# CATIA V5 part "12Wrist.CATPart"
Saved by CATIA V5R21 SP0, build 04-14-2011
Part number: Wrist
Bounding box of the stored display mesh (mm): x -30 to 20.5, y -302.172 to -247.172, z 287.191 to 317.191
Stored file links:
  C:\Users\水心\Desktop\Arm_Detailed_Design_Assembly_Manu\12Wrist.CATPart
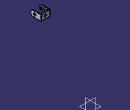
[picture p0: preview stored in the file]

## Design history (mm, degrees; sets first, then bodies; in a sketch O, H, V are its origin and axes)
Body1 (main body)
  DatumSurface1
  DatumCurve1
  DatumCurve2
  Plane1: stored without definition
  Plane2: stored without definition
  DatumCurve3
  Sketch1 on face of DatumSurface1, origin (0, -247.172, 0), H (-1, 0, 0), V (0, 0, 1)
    circle A1 centre (3, 310.6906) radius 1.25
    reference projected circle E1 centre (3, 310.6906) radius 1.25 from edge of DatumCurve2
    circle A2 centre (-5.5, 302.1906) radius 1.25
    circle A3 centre (3, 293.6906) radius 1.25
    circle A4 centre (11.5, 302.1906) radius 1.25
    line L1 (27, 317.1906) -> (-17.5, 317.1906)
    line L2 (-17.5, 317.1906) -> (-17.5, 287.1906)
    line L3 (-17.5, 287.1906) -> (27, 287.1906)
    line L4 (27, 287.1906) -> (27, 317.1906)
    reference intersected line E2 through (0, 302.1906) direction (-1, 0) from Plane1
    reference intersected line E3 through (3, 0) direction (0, -1) from Plane2
    circle A5 centre (3, 302.1906) radius 6
    reference projected circle E4 centre (3, 302.1906) radius 6 from edge of DatumCurve3
    length L2 = 30
    distance L1 E2 = 15
    length L3 = 44.5
    distance L2 E3 = 20.5
    coincidence: A1 E1, A5 E4
    horizontal: L1 H, L3 H
    vertical: L2 V, L4 V
  Pad1: profile Sketch1, direction (0, -1, 0), length 5
  Plane3 to Plane6: stored without definition
  DatumSurface2
  DatumSurface3
  Sketch2 on face of Pad1 from Sketch1.L2, origin (17.5, 0, 0), H (0, 1, 0), V (0, 0, 1)
    circle A1 centre (-249.672, 307.1906) radius 1.25
    point P1 (-249.672, 307.1906)
    circle A2 centre (-249.672, 297.1906) radius 1.25
    point P2 (-249.672, 297.1906)
    reference projected line E1 (-247.172, 317.1906) -> (-252.172, 317.1906) from edge [face of Pad1 from Sketch1.L1 | face of Pad1 from Sketch1.L2]
    reference projected line E2 (-252.172, 317.1906) -> (-252.172, 287.1906) from edge [end face of Pad1 | face of Pad1 from Sketch1.L2]
    reference projected line E3 (-247.172, 317.1906) -> (-247.172, 287.1906) from edge [face of Pad1 from Sketch1.L2 | start face of Pad1]
    reference projected line E4 (-247.172, 287.1906) -> (-252.172, 287.1906) from edge [face of Pad1 from Sketch1.L2 | face of Pad1 from Sketch1.L3]
    distance P1 E1 = 10
    radius A1 = 1.25
    distance P1 E2 = 2.5
    radius A2 = 1.25
    distance P2 E3 = 2.5
    distance P2 E4 = 10
  Pocket1: profile Sketch2, direction (-1, 0, 0), length 5
  Sketch3 on face of Pad1 from Sketch1.L4, origin (-27, 0, 0), H (0, -1, 0), V (0, 0, 1)
    circle A1 centre (249.672, 307.1906) radius 1.25
    point P1 (249.672, 307.1906)
    circle A2 centre (249.672, 297.1906) radius 1.25
    point P2 (249.672, 297.1906)
    reference projected line E1 (247.172, 287.1906) -> (252.172, 287.1906) from edge [face of Pad1 from Sketch1.L3 | face of Pad1 from Sketch1.L4]
    reference projected line E2 (247.172, 317.1906) -> (252.172, 317.1906) from edge [face of Pad1 from Sketch1.L4 | face of Pad1 from Sketch1.L1]
    reference projected line E3 (247.172, 287.1906) -> (247.172, 317.1906) from edge [face of Pad1 from Sketch1.L4 | start face of Pad1]
    reference projected line E4 (247.172, 287.1906) -> (247.172, 317.1906) from edge [face of Pad1 from Sketch1.L4 | start face of Pad1]
    radius A2 = 1.25
    radius A1 = 1.25
    distance P2 E1 = 10
    distance P1 E2 = 10
    distance P2 E3 = 2.5
    distance P1 E4 = 2.5
  Pocket2: profile Sketch3, direction (1, 0, 0), length 5
Body2
  Sketch4 on face of Pad1 from Sketch1.L4, origin (-27, 0, 0), H (0, -1, 0), V (0, 0, 1)
    point P1 (247.172, 317.1906)
    line L1 (247.172, 317.1906) -> (290.172, 317.1906)
    line L2 (302.172, 305.1906) -> (302.172, 299.1906)
    line L3 (290.172, 287.1906) -> (247.172, 287.1906)
    line L4 (247.172, 287.1906) -> (247.172, 317.1906)
    point P2 (302.172, 317.1906)
    reference projected line E1 (247.172, 317.1906) -> (252.172, 317.1906) from edge [face of Pad1 from Sketch1.L4 | face of Pad1 from Sketch1.L1]
    reference projected line E2 (247.172, 287.1906) -> (252.172, 287.1906) from edge [face of Pad1 from Sketch1.L3 | face of Pad1 from Sketch1.L4]
    arc A1 centre (290.172, 305.1906) radius 12 from (290.172, 317.1906) to (302.172, 305.1906) cw
    arc A2 centre (290.172, 299.1906) radius 12 from (290.172, 287.1906) to (302.172, 299.1906) ccw
    line L5 (259.172, 309.6906) -> (294.672, 309.6906)
    line L6 (294.672, 309.6906) -> (294.672, 294.6906)
    line L7 (294.672, 294.6906) -> (259.172, 294.6906)
    line L8 (259.172, 294.6906) -> (259.172, 309.6906)
    reference intersected line E3 through (0, 302.1906) direction (-1, 0) from Plane3
    reference intersected line E4 through (247.172, 0) direction (0, -1) from Plane5
    circle A3 centre (297.422, 306.1906) radius 2.5
    point P14 (297.422, 306.1906)
    reference intersected line E5 through (0, 302.1906) direction (-1, 0) from Plane6
    construction line L9 (276.922, 327.1248) -> (276.922, 250.7347)
    circle A4 centre (256.422, 306.1906) radius 2.5
    axis line L10 (326.5358, 302.1906) -> (252.172, 302.1906)
    circle A5 centre (297.422, 298.1906) radius 2.5
    circle A6 centre (256.422, 298.1906) radius 2.5
    circle A7 centre (249.672, 307.1906) radius 1.25
    point P22 (249.672, 307.1906)
    circle A8 centre (249.672, 297.1906) radius 1.25
    point P23 (249.672, 297.1906)
    reference projected line E6 (247.172, 317.1906) -> (252.172, 317.1906) from edge [face of Pad1 from Sketch1.L4 | face of Pad1 from Sketch1.L1]
    reference projected line E7 (247.172, 287.1906) -> (247.172, 317.1906) from edge [face of Pad2 | face of Pad1]
    line L11 (255.984, 315.21) -> (261.984, 315.21)
    line L12 (261.984, 315.21) -> (261.984, 312.21)
    line L13 (261.984, 312.21) -> (255.984, 312.21)
    line L14 (255.984, 312.21) -> (255.984, 315.21)
    distance P1 P2 = 55
    radius A1 = 12
    radius A2 = 12
    distance L5 E3 = 7.5
    length L6 = 15
    length L7 = 35.5
    distance E4 L8 = 12
    radius A3 = 2.5
    distance P14 E5 = 4
    distance L6 L9 = 17.75
    distance P14 L9 = 20.5
    distance L10 L5 = 7.5
    distance P22 E6 = 10
    radius A7 = 1.25
    distance P22 L4 = 2.5
    radius A8 = 1.25
    distance P23 L3 = 10
    distance P23 L4 = 2.5
    length L11 = 6
    length L12 = 3
    horizontal: L1 H, L3 H, L5 H, L7 H, L10 H, L11 H, L13 H
    vertical: L2 V, L4 V, L6 V, L8 V, L9 V, L12 V, L14 V
    coincidence: L1 E1, L3 E2, L1 P2, L2 P2, L4 E7
    tangency: A1 L1, A1 L2, A2 L3, A2 L2
    symmetry: A3 A4 L9, A3 A5 L10, A4 A6 L10
  Pad2: profile Sketch4, direction (-1, 0, 0), length 3
Body3
  Sketch5 on face of Pad1 from Sketch1.L2, origin (17.5, 0, 0), H (0, 1, 0), V (0, 0, 1)
    point P1 (-302.172, 317.1906)
    line L1 (-290.172, 317.1906) -> (-247.172, 317.1906)
    line L2 (-247.172, 317.1906) -> (-247.172, 287.1906)
    line L3 (-247.172, 287.1906) -> (-290.172, 287.1906)
    line L4 (-302.172, 299.1906) -> (-302.172, 305.1906)
    point P2 (-247.172, 317.1906)
    reference projected line E1 (-247.172, 317.1906) -> (-247.172, 287.1906) from edge [face of Pad1 from Sketch1.L2 | start face of Pad1]
    reference projected line E2 (-247.172, 287.1906) -> (-252.172, 287.1906) from edge [face of Pad1 from Sketch1.L2 | face of Pad1 from Sketch1.L3]
    reference projected line E3 (-247.172, 317.1906) -> (-252.172, 317.1906) from edge [face of Pad1 from Sketch1.L1 | face of Pad1 from Sketch1.L2]
    arc A1 centre (-290.172, 299.1906) radius 12 from (-290.172, 287.1906) to (-302.172, 299.1906) cw
    arc A2 centre (-290.172, 305.1906) radius 12 from (-290.172, 317.1906) to (-302.172, 305.1906) ccw
    circle A3 centre (-282.172, 302.1906) radius 6.9
    point P10 (-282.172, 302.1906)
    circle A4 centre (-249.672, 307.1906) radius 1.25
    point P11 (-249.672, 307.1906)
    circle A5 centre (-249.672, 297.1906) radius 1.25
    point P12 (-249.672, 297.1906)
    radius A1 = 12
    distance P1 P2 = 55
    radius A2 = 12
    distance P10 L2 = 35
    distance P10 L1 = 15
    radius A3 = 6.9
    radius A4 = 1.25
    distance P11 L2 = 2.5
    distance P11 L1 = 10
    radius A5 = 1.25
    distance P12 L2 = 2.5
    distance P12 L3 = 10
    horizontal: L1 H, L3 H
    vertical: L2 V, L4 V
    coincidence: E1 L2, E2 L3, L1 E3, L1 P1, L4 P1
    tangency: A1 L3, A1 L4, A2 L1, A2 L4
  Pad3: profile Sketch5, direction (1, 0, 0), length 3
  Sketch6 on face of Pad3 from Sketch5.L1, origin (0, 0, 317.1906), H (1, 0, 0), V (0, 1, 0)
    circle A1 centre (19, -282.172) radius 0.75
    point P1 (19, -282.172)
    reference projected line E1 (17.5, -302.172) -> (20.5, -302.172) from edge [face of Pad3 from Sketch5.L4 | face of Pad3 from Sketch5.A2]
    reference projected line E2 (17.5, -247.172) -> (17.5, -290.172) from edge [start face of Pad3 | face of Pad3 from Sketch5.L1]
    radius A1 = 0.75
    distance E1 P1 = 20
    distance P1 E2 = 1.5
  Pocket3: profile Sketch6, direction (0, 0, -1), through (limit type 3)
